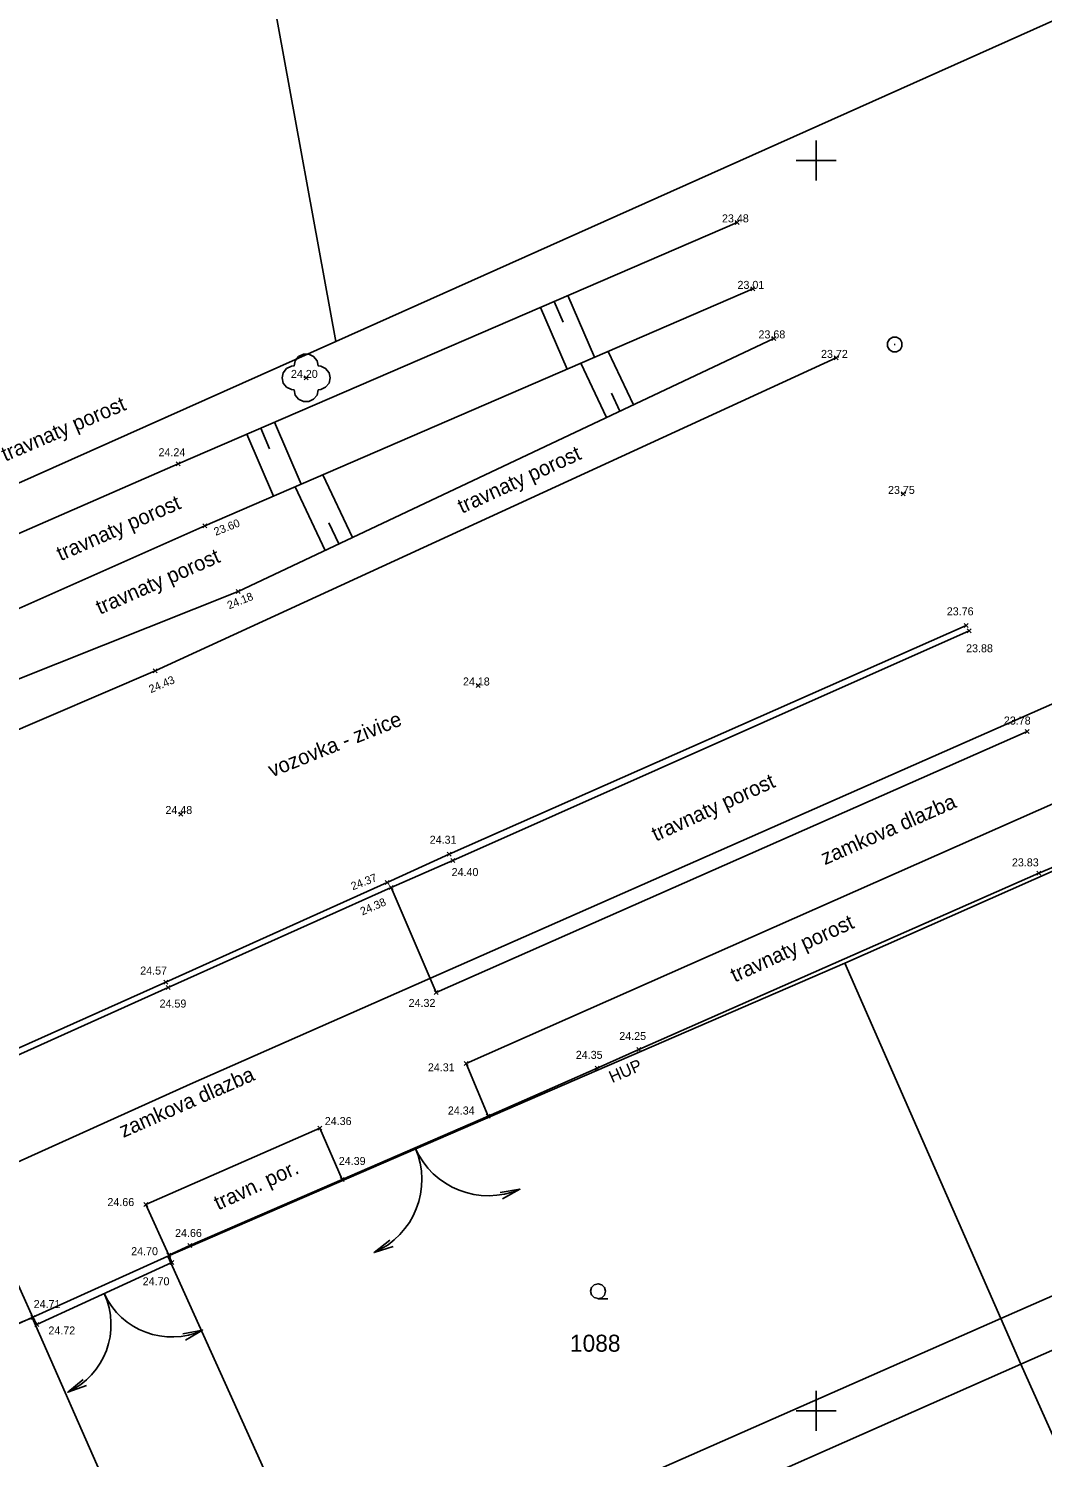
# Model space of a CAD drawing. Extents: x -772300 to -772183, y -1034101 to -1034019.
# Drawn here: x -772240.75 to -772220.48, y -1034075.93 to -1034047.37 of the extents above; entities that cross this region are included whole.
import ezdxf

# ---------------------------------------------------------------- set-up
doc = ezdxf.new("R2010")
doc.units = 0
for name, color, linetype in [('body', 7, 'Continuous'), ('HUP_el', 7, 'Continuous'), ('KM_body', 7, 'Continuous'), ('KM_hranice', 7, 'Continuous'), ('KM_mezni_znaky', 7, 'Continuous'), ('KM_parcelni_cisla', 7, 'Continuous'), ('KM_vnitrni_kresba', 7, 'Continuous'), ('mistni_popis', 7, 'Continuous'), ('oddeleni_ploch', 7, 'Continuous'), ('oploceni', 7, 'Continuous'), ('souradnicova_sit', 7, 'Continuous'), ('stromy_kere', 7, 'Continuous'), ('svah_srafy_vrstevnice', 7, 'Continuous'), ('svahy', 7, 'Continuous'), ('vyskove_koty', 7, 'Continuous')]:
    doc.layers.add(name, color=color, linetype=linetype)

msp = doc.modelspace()

# ---------------------------------------------------------------- linework, layer by layer
at = {"layer": 'body'}
for p, q in [((-772226.54, -1034051.28), (-772226.62, -1034051.2)), ((-772226.62, -1034051.28), (-772226.54, -1034051.2)), ((-772226.23, -1034052.61), (-772226.31, -1034052.53)), ((-772226.31, -1034052.61), (-772226.23, -1034052.53)), ((-772225.81, -1034053.6), (-772225.89, -1034053.52)), ((-772225.89, -1034053.6), (-772225.81, -1034053.52)), ((-772224.56, -1034053.99), (-772224.64, -1034053.91)), ((-772224.64, -1034053.99), (-772224.56, -1034053.91)), ((-772235.16, -1034054.39), (-772235.24, -1034054.31)), ((-772235.24, -1034054.39), (-772235.16, -1034054.31)), ((-772237.72, -1034056.11), (-772237.8, -1034056.03)), ((-772237.8, -1034056.11), (-772237.72, -1034056.03)), ((-772223.22, -1034056.71), (-772223.3, -1034056.63)), ((-772223.3, -1034056.71), (-772223.22, -1034056.63)), ((-772237.19, -1034057.35), (-772237.27, -1034057.27)), ((-772237.27, -1034057.35), (-772237.19, -1034057.27)), ((-772236.52, -1034058.66), (-772236.6, -1034058.58)), ((-772236.6, -1034058.66), (-772236.52, -1034058.58)), ((-772221.96, -1034059.34), (-772222.04, -1034059.26)), ((-772222.04, -1034059.34), (-772221.96, -1034059.26)), ((-772221.9, -1034059.45), (-772221.98, -1034059.37)), ((-772221.98, -1034059.45), (-772221.9, -1034059.37)), ((-772238.18, -1034060.25), (-772238.26, -1034060.17)), ((-772238.26, -1034060.25), (-772238.18, -1034060.17)), ((-772231.72, -1034060.54), (-772231.8, -1034060.46)), ((-772231.8, -1034060.54), (-772231.72, -1034060.46)), ((-772220.74, -1034061.46), (-772220.82, -1034061.38)), ((-772220.82, -1034061.46), (-772220.74, -1034061.38)), ((-772237.67, -1034063.11), (-772237.75, -1034063.03)), ((-772237.75, -1034063.11), (-772237.67, -1034063.03)), ((-772232.3, -1034063.91), (-772232.38, -1034063.83)), ((-772232.38, -1034063.91), (-772232.3, -1034063.83)), ((-772232.23, -1034064.04), (-772232.31, -1034063.96)), ((-772232.31, -1034064.04), (-772232.23, -1034063.96)), ((-772233.54, -1034064.48), (-772233.62, -1034064.4)), ((-772233.62, -1034064.48), (-772233.54, -1034064.4)), ((-772220.51, -1034064.29), (-772220.59, -1034064.21)), ((-772220.59, -1034064.29), (-772220.51, -1034064.21)), ((-772233.46, -1034064.58), (-772233.54, -1034064.5)), ((-772233.54, -1034064.58), (-772233.46, -1034064.5)), ((-772237.97, -1034066.47), (-772238.05, -1034066.39)), ((-772238.05, -1034066.47), (-772237.97, -1034066.39)), ((-772237.92, -1034066.58), (-772238, -1034066.5)), ((-772238, -1034066.58), (-772237.92, -1034066.5)), ((-772232.56, -1034066.68), (-772232.64, -1034066.6)), ((-772232.64, -1034066.68), (-772232.56, -1034066.6)), ((-772228.51, -1034067.82), (-772228.59, -1034067.74)), ((-772228.59, -1034067.82), (-772228.51, -1034067.74)), ((-772231.96, -1034068.1), (-772232.04, -1034068.02)), ((-772232.04, -1034068.1), (-772231.96, -1034068.02)), ((-772229.34, -1034068.19), (-772229.42, -1034068.11)), ((-772229.42, -1034068.19), (-772229.34, -1034068.11)), ((-772234.89, -1034069.39), (-772234.97, -1034069.31)), ((-772234.97, -1034069.39), (-772234.89, -1034069.31)), ((-772231.52, -1034069.15), (-772231.6, -1034069.07)), ((-772231.6, -1034069.15), (-772231.52, -1034069.07)), ((-772234.44, -1034070.42), (-772234.52, -1034070.34)), ((-772234.52, -1034070.42), (-772234.44, -1034070.34)), ((-772238.37, -1034070.92), (-772238.45, -1034070.84)), ((-772238.45, -1034070.92), (-772238.37, -1034070.84)), ((-772237.91, -1034071.93), (-772237.99, -1034071.85)), ((-772237.99, -1034071.93), (-772237.91, -1034071.85)), ((-772237.49, -1034071.74), (-772237.57, -1034071.66)), ((-772237.57, -1034071.74), (-772237.49, -1034071.66)), ((-772237.85, -1034072.08), (-772237.93, -1034072)), ((-772237.93, -1034072.08), (-772237.85, -1034072)), ((-772240.63, -1034073.18), (-772240.71, -1034073.1)), ((-772240.71, -1034073.18), (-772240.63, -1034073.1)), ((-772240.55, -1034073.32), (-772240.63, -1034073.24)), ((-772240.63, -1034073.32), (-772240.55, -1034073.24))]:
    msp.add_line(p, q, dxfattribs=at)
at = {"layer": 'HUP_el'}
for p, q in [((-772220.55, -1034064.25), (-772219.72, -1034063.9)), ((-772229.38, -1034068.15), (-772228.55, -1034067.78))]:
    msp.add_line(p, q, dxfattribs=at)
at = {"layer": 'KM_body'}
msp.add_lwpolyline([(-772229.362, -1034072.759), (-772229.438, -1034072.739), (-772229.492, -1034072.685), (-772229.512, -1034072.611), (-772229.492, -1034072.537), (-772229.438, -1034072.483), (-772229.364, -1034072.463), (-772229.29, -1034072.483), (-772229.236, -1034072.537), (-772229.216, -1034072.613), (-772229.236, -1034072.689), (-772229.29, -1034072.743), (-772229.366, -1034072.763), (-772229.166, -1034072.763)], dxfattribs=at)
at = {"layer": 'KM_hranice'}
for p, q in [((-772234.61, -1034053.62), (-772240.956, -1034018.905)), ((-772183.472, -1034044.635), (-772237.52, -1034068.47)), ((-772219.18, -1034046.72), (-772234.61, -1034053.62)), ((-772234.61, -1034053.62), (-772250.12, -1034060.55)), ((-772224.43, -1034066.05), (-772211.03, -1034060.13)), ((-772237.97, -1034071.91), (-772224.43, -1034066.05)), ((-772224.43, -1034066.05), (-772221.31, -1034073.16)), ((-772237.52, -1034068.47), (-772299.808, -1034096.549)), ((-772212.16, -1034069.14), (-772221.31, -1034073.16)), ((-772240.68, -1034073.14), (-772237.97, -1034071.91)), ((-772224.901, -1034100.835), (-772237.97, -1034071.91)), ((-772276.27, -1034088.94), (-772240.68, -1034073.14)), ((-772240.68, -1034073.14), (-772231.15, -1034094.77)), ((-772221.31, -1034073.16), (-772230.54, -1034077.22)), ((-772221.31, -1034073.16), (-772220.91, -1034074.07)), ((-772220.91, -1034074.07), (-772217.91, -1034080.77))]:
    msp.add_line(p, q, dxfattribs=at)
at = {"layer": 'KM_mezni_znaky'}
msp.add_line((-772223.44, -1034053.68), (-772223.42, -1034053.68), dxfattribs=at)
msp.add_lwpolyline([(-772223.392, -1034053.536), (-772223.324, -1034053.574), (-772223.286, -1034053.642), (-772223.286, -1034053.72), (-772223.324, -1034053.788), (-772223.392, -1034053.826), (-772223.47, -1034053.826), (-772223.538, -1034053.788), (-772223.576, -1034053.72), (-772223.576, -1034053.642), (-772223.538, -1034053.574), (-772223.47, -1034053.536)], close=True, dxfattribs=at)
at = {"layer": 'KM_vnitrni_kresba'}
for p, q in [((-772213.73, -1034070.92), (-772220.91, -1034074.07)), ((-772220.91, -1034074.07), (-772228.15, -1034077.27))]:
    msp.add_line(p, q, dxfattribs=at)
at = {"layer": 'oddeleni_ploch'}
for p, q in [((-772224.6, -1034053.95), (-772238.22, -1034060.21)), ((-772247.44, -1034064.15), (-772238.22, -1034060.21)), ((-772241.13, -1034072.1), (-772240.67, -1034073.14))]:
    msp.add_line(p, q, dxfattribs=at)
for points in [[(-772243.71, -1034068.97), (-772242.79, -1034068.57), (-772238.01, -1034066.43), (-772233.58, -1034064.44), (-772232.34, -1034063.87), (-772222, -1034059.3)], [(-772233.5, -1034064.54), (-772232.27, -1034064), (-772221.94, -1034059.41)], [(-772242.72, -1034068.68), (-772237.96, -1034066.54), (-772233.5, -1034064.54), (-772232.6, -1034066.64), (-772220.78, -1034061.42)], [(-772231.56, -1034069.11), (-772232, -1034068.06), (-772220.15, -1034062.81)], [(-772237.95, -1034071.89), (-772238.41, -1034070.88), (-772234.93, -1034069.35), (-772234.48, -1034070.38)]]:
    msp.add_lwpolyline(points, dxfattribs=at)
at = {"layer": 'oploceni'}
for p, q in [((-772228.55, -1034067.78), (-772220.55, -1034064.25)), ((-772231.56, -1034069.11), (-772229.38, -1034068.15)), ((-772231.56, -1034069.11), (-772234.48, -1034070.38)), ((-772237.53, -1034071.7), (-772234.48, -1034070.38)), ((-772237.89, -1034072.04), (-772240.59, -1034073.28))]:
    msp.add_line(p, q, dxfattribs=at)
for points in [[(-772231.275, -1034070.766), (-772230.926, -1034070.571), (-772231.321, -1034070.635)], [(-772233.528, -1034071.594), (-772233.844, -1034071.839), (-772233.463, -1034071.717)], [(-772237.89, -1034072.04), (-772237.95, -1034071.89), (-772237.53, -1034071.7)], [(-772241.09, -1034073.31), (-772240.67, -1034073.14), (-772240.59, -1034073.28)], [(-772237.617, -1034073.591), (-772237.271, -1034073.39), (-772237.665, -1034073.461)], [(-772239.659, -1034074.377), (-772239.969, -1034074.63), (-772239.591, -1034074.498)]]:
    msp.add_lwpolyline(points, dxfattribs=at)
for centre, radius, start, end in [((-772234.48, -1034070.38), 1.592, 293.5514, 23.5057), ((-772231.56, -1034069.11), 1.592, 203.5057, 293.4601), ((-772240.59, -1034073.28), 1.486, 294.713, 24.6674), ((-772237.89, -1034072.04), 1.486, 204.6674, 294.6218)]:
    msp.add_arc(centre, radius, start, end, dxfattribs=at)
at = {"layer": 'souradnicova_sit'}
for p, q in [((-772225, -1034049.6), (-772225, -1034050.4)), ((-772225.4, -1034050), (-772224.6, -1034050)), ((-772225, -1034074.6), (-772225, -1034075.4)), ((-772225.4, -1034075), (-772224.6, -1034075))]:
    msp.add_line(p, q, dxfattribs=at)
at = {"layer": 'stromy_kere'}
msp.add_lwpolyline([(-772234.72, -1034054.35), (-772234.744, -1034054.453), (-772234.811, -1034054.537), (-772234.907, -1034054.583), (-772234.96, -1034054.59), (-772234.984, -1034054.693), (-772235.051, -1034054.777), (-772235.147, -1034054.823), (-772235.255, -1034054.823), (-772235.351, -1034054.777), (-772235.418, -1034054.693), (-772235.442, -1034054.59), (-772235.495, -1034054.583), (-772235.591, -1034054.537), (-772235.658, -1034054.453), (-772235.682, -1034054.35), (-772235.658, -1034054.247), (-772235.591, -1034054.163), (-772235.495, -1034054.117), (-772235.442, -1034054.11), (-772235.418, -1034054.007), (-772235.351, -1034053.923), (-772235.255, -1034053.877), (-772235.147, -1034053.877), (-772235.051, -1034053.923), (-772234.984, -1034054.007), (-772234.96, -1034054.11), (-772234.907, -1034054.117), (-772234.811, -1034054.163), (-772234.744, -1034054.247)], close=True, dxfattribs=at)
msp.add_lwpolyline([(-772235.212, -1034054.35), (-772235.2, -1034054.35), (-772235.188, -1034054.35)], dxfattribs=at)
at = {"layer": 'svah_srafy_vrstevnice'}
for p, q in [((-772229.966, -1034052.703), (-772229.432, -1034053.938)), ((-772230.516, -1034052.941), (-772229.983, -1034054.176)), ((-772230.241, -1034052.822), (-772230.063, -1034053.233)), ((-772228.654, -1034054.885), (-772229.158, -1034053.819)), ((-772229.197, -1034055.141), (-772229.709, -1034054.057)), ((-772228.925, -1034055.013), (-772229.094, -1034054.655)), ((-772235.835, -1034055.238), (-772235.301, -1034056.476)), ((-772236.386, -1034055.476), (-772235.851, -1034056.714)), ((-772236.11, -1034055.357), (-772235.932, -1034055.769)), ((-772234.277, -1034057.542), (-772234.869, -1034056.289)), ((-772234.82, -1034057.798), (-772235.42, -1034056.527)), ((-772234.549, -1034057.67), (-772234.747, -1034057.25))]:
    msp.add_line(p, q, dxfattribs=at)
at = {"layer": 'svahy'}
for points in [[(-772226.58, -1034051.24), (-772237.76, -1034056.07), (-772247.37, -1034060.27), (-772250.03, -1034061.94)], [(-772226.27, -1034052.57), (-772237.23, -1034057.31), (-772249.77, -1034062.88)], [(-772225.85, -1034053.56), (-772236.56, -1034058.62), (-772248.26, -1034063.28), (-772249.81, -1034063.62)]]:
    msp.add_lwpolyline(points, dxfattribs=at)

# ---------------------------------------------------------------- texts
at = {"layer": 'KM_parcelni_cisla'}
msp.add_text('1088', height=0.34, dxfattribs=at).set_placement((-772229.926, -1034073.821))
at = {"layer": 'mistni_popis'}
for s, height, rotation, p in [('travnaty porost', 0.3, 23.2048, (-772241.217, -1034056.026)), ('travnaty porost', 0.3, 24.5799, (-772232.086, -1034057.068)), ('travnaty porost', 0.3, 23.6059, (-772240.111, -1034058.016)), ('travnaty porost', 0.3, 23.6059, (-772239.325, -1034059.087)), ('vozovka - zivice', 0.3, 21.887, (-772235.887, -1034062.341)), ('travnaty porost', 0.3, 24.5799, (-772228.207, -1034063.623)), ('zamkova dlazba', 0.3, 23.7205, (-772224.827, -1034064.095)), ('travnaty porost', 0.3, 24.5799, (-772226.629, -1034066.442)), ('zamkova dlazba', 0.3, 23.7205, (-772238.858, -1034069.548)), ('HUP', 0.24, 23.4913, (-772229.081, -1034068.452)), ('travn. por.', 0.3, 24.6945, (-772236.959, -1034070.997))]:
    msp.add_text(s, height=height, rotation=rotation, dxfattribs=at).set_placement(p)
at = {"layer": 'vyskove_koty'}
for s, p in [('23.48', (-772226.885, -1034051.24)), ('23.01', (-772226.575, -1034052.57)), ('23.68', (-772226.155, -1034053.56)), ('23.72', (-772224.905, -1034053.95)), ('24.20', (-772235.505, -1034054.35)), ('24.24', (-772238.153, -1034055.916)), ('23.75', (-772223.565, -1034056.67)), ('23.76', (-772222.39, -1034059.097)), ('23.88', (-772222.003, -1034059.836)), ('24.18', (-772232.065, -1034060.5)), ('23.78', (-772221.248, -1034061.281)), ('24.48', (-772238.015, -1034063.07)), ('24.31', (-772232.73, -1034063.664)), ('24.40', (-772232.292, -1034064.311)), ('23.83', (-772221.087, -1034064.117)), ('24.57', (-772238.519, -1034066.28)), ('24.32', (-772233.152, -1034066.927)), ('24.59', (-772238.132, -1034066.94)), ('24.25', (-772228.939, -1034067.589)), ('24.35', (-772229.808, -1034067.965)), ('24.31', (-772232.766, -1034068.215)), ('24.34', (-772232.367, -1034069.078)), ('24.36', (-772234.828, -1034069.289)), ('24.39', (-772234.548, -1034070.087)), ('24.66', (-772239.175, -1034070.909)), ('24.66', (-772237.822, -1034071.527)), ('24.70', (-772238.7, -1034071.891)), ('24.70', (-772238.47, -1034072.493)), ('24.71', (-772240.65, -1034072.948)), ('24.72', (-772240.355, -1034073.476))]:
    msp.add_text(s, height=0.16, dxfattribs=at).set_placement(p)
for s, rotation, p in [('23.60', 21.3713, (-772237.008, -1034057.508)), ('24.18', 21.9443, (-772236.74, -1034058.979)), ('24.43', 23.0902, (-772238.305, -1034060.655)), ('24.37', 21.0276, (-772234.268, -1034064.596)), ('24.38', 23.5486, (-772234.077, -1034065.1))]:
    msp.add_text(s, height=0.16, rotation=rotation, dxfattribs=at).set_placement(p)

doc.saveas('drawing.dxf')
